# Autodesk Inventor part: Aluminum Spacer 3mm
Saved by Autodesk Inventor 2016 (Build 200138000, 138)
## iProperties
Created: 2016-03
Part Number: Aluminum Spacer 3mm
Material: Generic
Document SubType Name: Modeling
Designer: bongo_000
Density: 1 g/cm^3
Appearance: Default
Author: bongo_000
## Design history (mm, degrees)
feature "CHAMFER1"
body "Solid1"
